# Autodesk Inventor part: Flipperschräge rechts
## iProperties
Created: 2017-04
Part Number: Flipperschräge rechts
Material: Standard
Document SubType Name: Blech
Designer: Acer
Density: 1 g/cm^3
Sheet Metal Rule: Standard_mm
Author: Acer
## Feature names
1. Extrusion1
2. Rundung1 [Fillet]
3. Rundung2 [Fillet]
4. Rundung3 [Fillet]
